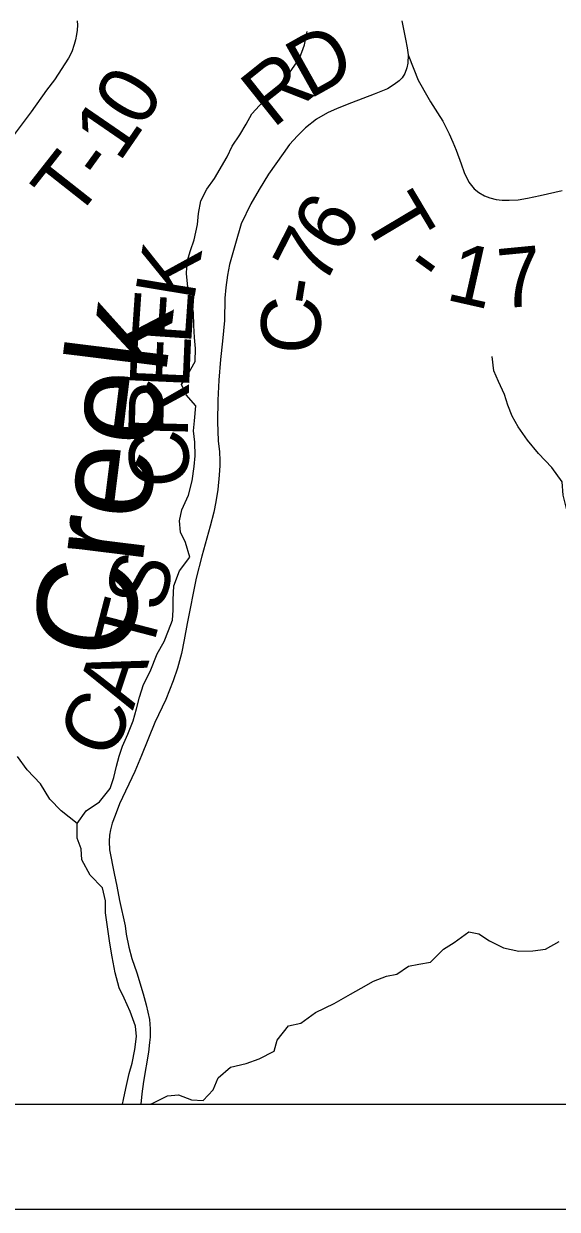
# Model space of a CAD drawing. Extents: x 0 to 34, y 0 to 22.
# Drawn here: x 4.027 to 4.535, y 14 to 15.129 of the extents above; entities that cross this region are included whole.
import ezdxf

# ---------------------------------------------------------------- set-up
doc = ezdxf.new("R2010")
doc.units = 0
for name, color, linetype in [('GM_X_County_Road', 7, 'Continuous'), ('GM_X_County_Road_Text', 7, 'Continuous'), ('GM_X_Minor_River', 7, 'Continuous'), ('GM_X_Minor_River_Text', 7, 'Continuous'), ('GM_X_Rail_Line', 7, 'Continuous'), ('GM_X_Township_Road', 7, 'Continuous'), ('GM_X_Township_Road_Text', 7, 'Continuous'), ('SH_Cut_Line', 7, 'Continuous'), ('SH_Data', 7, 'Continuous')]:
    doc.layers.add(name, color=color, linetype=linetype)

msp = doc.modelspace()

# ---------------------------------------------------------------- linework, layer by layer
at = {"layer": 'GM_X_County_Road'}
msp.add_lwpolyline([(4.387, 15.132), (4.3906, 15.1144), (4.3922, 15.1061), (4.3933, 15.0996), (4.3929, 15.0916), (4.392, 15.0871), (4.3899, 15.0817), (4.3874, 15.0777), (4.3845, 15.0747), (4.3799, 15.0712), (4.3734, 15.0672), (4.3609, 15.0622), (4.3393, 15.0537), (4.3256, 15.0485), (4.3164, 15.0443), (4.3057, 15.0382), (4.2954, 15.0301), (4.2877, 15.0224), (4.2802, 15.0141), (4.274, 15.0057), (4.26, 14.9859), (4.2512, 14.9714), (4.2432, 14.9575), (4.2339, 14.9386), (4.2285, 14.9198), (4.223, 14.8999), (4.2208, 14.8898), (4.2192, 14.8781), (4.2184, 14.8678), (4.218, 14.8466), (4.2161, 14.8268), (4.2142, 14.8094), (4.2127, 14.7898), (4.2117, 14.7705), (4.2114, 14.7499), (4.212, 14.732), (4.2133, 14.7214), (4.2136, 14.7133), (4.2135, 14.7085), (4.213, 14.6993), (4.2116, 14.6855), (4.2099, 14.6739), (4.2078, 14.6639), (4.2045, 14.6505), (4.1965, 14.6222), (4.1912, 14.6011), (4.1825, 14.558), (4.1796, 14.5423), (4.177, 14.5292), (4.1734, 14.5155), (4.169, 14.5034), (4.1621, 14.4856), (4.1517, 14.4637), (4.139, 14.4323), (4.1326, 14.417), (4.1181, 14.3861), (4.1138, 14.3752), (4.1111, 14.3677), (4.1095, 14.3615), (4.1086, 14.3564), (4.1081, 14.3503), (4.1085, 14.3425), (4.113, 14.3198), (4.1153, 14.3078), (4.118, 14.2942), (4.1234, 14.2701), (4.1245, 14.2619), (4.127, 14.2498), (4.1299, 14.2389), (4.1345, 14.2252), (4.1406, 14.2052), (4.1433, 14.1948), (4.1466, 14.1808), (4.1473, 14.1719), (4.1471, 14.1638), (4.1466, 14.159), (4.1457, 14.1495), (4.141, 14.1216), (4.1393, 14.1101), (4.1383, 14.1)], dxfattribs=at)
at = {"layer": 'GM_X_Minor_River'}
for points in [[(4.1372, 14.4879), (4.1409, 14.4997), (4.1472, 14.5123), (4.1538, 14.5291), (4.1605, 14.5409), (4.1646, 14.5512), (4.1686, 14.5611), (4.1693, 14.5706), (4.1692, 14.5805), (4.1698, 14.5937), (4.1753, 14.6082), (4.185, 14.6212), (4.181, 14.6352), (4.176, 14.645), (4.1751, 14.6556), (4.1773, 14.6663), (4.1839, 14.68), (4.1872, 14.6937), (4.1893, 14.7074), (4.19, 14.7176), (4.1898, 14.7305), (4.1886, 14.7415), (4.1896, 14.751), (4.1909, 14.7651), (4.1817, 14.7756), (4.1771, 14.7854), (4.183, 14.795), (4.1901, 14.8075), (4.1903, 14.8197), (4.1894, 14.8303), (4.1889, 14.8417), (4.1884, 14.8538), (4.1868, 14.864), (4.1832, 14.8784), (4.1819, 14.8913), (4.1826, 14.9027), (4.1858, 14.9133), (4.1891, 14.9232), (4.1924, 14.9381), (4.1934, 14.9483), (4.1955, 14.9605), (4.2011, 14.9716), (4.2086, 14.9819), (4.2205, 15.0025), (4.2253, 15.0124), (4.2327, 15.0235), (4.2387, 15.0334), (4.2443, 15.0433), (4.2551, 15.0552), (4.2694, 15.069), (4.2802, 15.0824), (4.2895, 15.0962), (4.2943, 15.1091), (4.2968, 15.1217)], [(4.5707, 14.6266), (4.565, 14.6368), (4.5592, 14.6481), (4.5485, 14.6567), (4.5442, 14.6676), (4.541, 14.6801), (4.5401, 14.693), (4.5301, 14.7066), (4.5175, 14.7197), (4.5071, 14.7325), (4.4982, 14.7453), (4.4924, 14.7555), (4.4881, 14.766), (4.485, 14.7759), (4.4792, 14.7883), (4.4749, 14.7985), (4.4732, 14.8122)], [(4.121, 14.1), (4.1219, 14.1046), (4.124, 14.1149), (4.1273, 14.1293), (4.1302, 14.1392), (4.1327, 14.1521), (4.1341, 14.1647), (4.1332, 14.1745), (4.1281, 14.1885), (4.1223, 14.201), (4.1176, 14.2108), (4.1137, 14.2251), (4.1109, 14.2403), (4.1088, 14.2535), (4.1064, 14.2691), (4.1047, 14.2823), (4.1046, 14.2937), (4.1018, 14.3062), (4.0899, 14.3182), (4.0821, 14.3329), (4.0813, 14.3432), (4.0777, 14.3534), (4.0776, 14.3674), (4.0861, 14.3796), (4.0989, 14.3881), (4.109, 14.4007), (4.1127, 14.4114), (4.1152, 14.4221), (4.1178, 14.4316), (4.1207, 14.4411), (4.1259, 14.4525), (4.131, 14.4651), (4.1343, 14.4765), (4.1372, 14.4879)], [(4.0776, 14.3674), (4.0623, 14.3794), (4.0515, 14.3906), (4.0426, 14.4053), (4.03, 14.4185), (4.0207, 14.4313)], [(4.1476, 14.1), (4.1503, 14.1015), (4.1639, 14.1081), (4.1741, 14.109), (4.1867, 14.1042), (4.1977, 14.1035), (4.2074, 14.1139), (4.2119, 14.1253), (4.2239, 14.1353), (4.2386, 14.1389), (4.2511, 14.1432), (4.2654, 14.1506), (4.2683, 14.1612), (4.2792, 14.1746), (4.2909, 14.1774), (4.3048, 14.1874), (4.3225, 14.1959), (4.3383, 14.2048), (4.3485, 14.2106), (4.3602, 14.2172), (4.3726, 14.2219), (4.3825, 14.2239), (4.3934, 14.2316), (4.4032, 14.2336), (4.4146, 14.2353), (4.4269, 14.2479), (4.4371, 14.2541), (4.451, 14.2641), (4.4605, 14.2623), (4.4708, 14.2556), (4.4842, 14.2489), (4.4986, 14.246), (4.5119, 14.2462), (4.524, 14.2478), (4.5372, 14.2552)]]:
    msp.add_lwpolyline(points, dxfattribs=at)
at = {"layer": 'GM_X_Rail_Line'}
msp.add_lwpolyline([(2.1, 18.7171), (2.1, 14.1), (4.5781, 14.1), (4.5658, 14.9668), (4.5509, 15.5331), (4.5478, 16.582), (4.5489, 17.6578), (4.5474, 17.7028), (4.5429, 17.9404), (4.5419, 17.9684), (4.5402, 18.2851), (4.5408, 18.3763), (4.5397, 18.3961), (4.5397, 18.4045), (4.5399, 18.4424), (4.5403, 18.5054), (4.5462, 18.6416), (3.8456, 18.6615), (3.8442, 18.6615), (2.9234, 18.6945), (2.9222, 18.6946), (2.7892, 18.6993), (2.7864, 18.6994)], close=True, dxfattribs=at)
at = {"layer": 'GM_X_Township_Road'}
for points in [[(4.0777, 15.132), (4.0779, 15.1279), (4.0775, 15.1231), (4.0771, 15.1189), (4.076, 15.1139), (4.0747, 15.1093), (4.0726, 15.1023), (4.0695, 15.0965), (4.0559, 15.0757), (4.0485, 15.0659), (4.0339, 15.0454), (4.0139, 15.0187)], [(4.3933, 15.0996), (4.3985, 15.0858), (4.4028, 15.0753), (4.4118, 15.0593), (4.4146, 15.0548), (4.4213, 15.0442), (4.4262, 15.0365), (4.4295, 15.0301), (4.4324, 15.0244), (4.4359, 15.0164), (4.4388, 15.0089), (4.4437, 14.9956), (4.4466, 14.9876), (4.4509, 14.9784), (4.456, 14.9719), (4.4607, 14.9685), (4.466, 14.9654), (4.4711, 14.9634), (4.4772, 14.9618), (4.4827, 14.961), (4.4895, 14.961), (4.4981, 14.9616), (4.5068, 14.9631), (4.5191, 14.9656), (4.54, 14.9702)]]:
    msp.add_lwpolyline(points, dxfattribs=at)
at = {"layer": 'SH_Cut_Line'}
msp.add_lwpolyline([(2.1, 14.1), (4.5781, 14.1), (4.5658, 14.9668), (4.5509, 15.5331), (4.5478, 16.582), (4.5489, 17.6578), (4.8158, 17.6467), (4.9624, 17.6496), (4.9797, 17.6498), (5.2052, 17.638), (5.3403, 17.635), (5.6743, 17.6274), (5.6656, 16.9939), (5.6628, 16.7899), (5.6628, 16.7878), (5.6614, 16.7344), (5.6594, 16.6485), (5.9824, 16.6436), (7.149, 16.6283)], dxfattribs=at)
at = {"layer": 'SH_Data'}
for p, q in [((2.1, 14.1), (8.9, 14.1)), ((2, 14), (9, 14))]:
    msp.add_line(p, q, dxfattribs=at)

# ---------------------------------------------------------------- texts
at = {"layer": 'GM_X_County_Road_Text'}
for s, rotation, p in [('D', 29.2867, (4.2986, 15.0566)), ('R', 38.6171, (4.2641, 15.0288)), ('6', 57.7519, (4.3278, 14.9073)), ('7', 62.9276, (4.3125, 14.8773)), ('K', 80.6293, (4.1888, 14.864)), ('-', 80.7802, (4.3102, 14.8587)), ('E', 86.0454, (4.1861, 14.823)), ('C', 88.3176, (4.309, 14.814)), ('E', 87.5008, (4.1842, 14.7809)), ('R', 88.4816, (4.183, 14.7345)), ('C', 93.03, (4.1855, 14.6891)), ('S', 75.5256, (4.1584, 14.5673)), ('T', 75.4439, (4.1477, 14.5261)), ('A', 71.64, (4.1307, 14.4747)), ('C', 66.2341, (4.1098, 14.4265))]:
    msp.add_text(s, height=0.0568, rotation=rotation, dxfattribs=at).set_placement(p)
at = {"layer": 'GM_X_Minor_River_Text'}
msp.add_text('Creek', height=0.09469, rotation=82.9278, dxfattribs=at).set_placement((4.1283, 14.5217))
at = {"layer": 'GM_X_Township_Road_Text'}
for s, rotation, p in [('0', 58.8808, (4.1396, 15.0282)), ('1', 55.5248, (4.1178, 14.9963)), ('T', 51.7826, (4.0754, 14.9407)), ('-', 54.134, (4.1032, 14.9762)), ('T', 300.775, (4.3477, 14.9453)), ('1', 347.3046, (4.4278, 14.8666)), ('7', 5.5228, (4.4812, 14.8577)), ('-', 324.1342, (4.3864, 14.8904))]:
    msp.add_text(s, height=0.0568, rotation=rotation, dxfattribs=at).set_placement(p)

doc.saveas('drawing.dxf')
